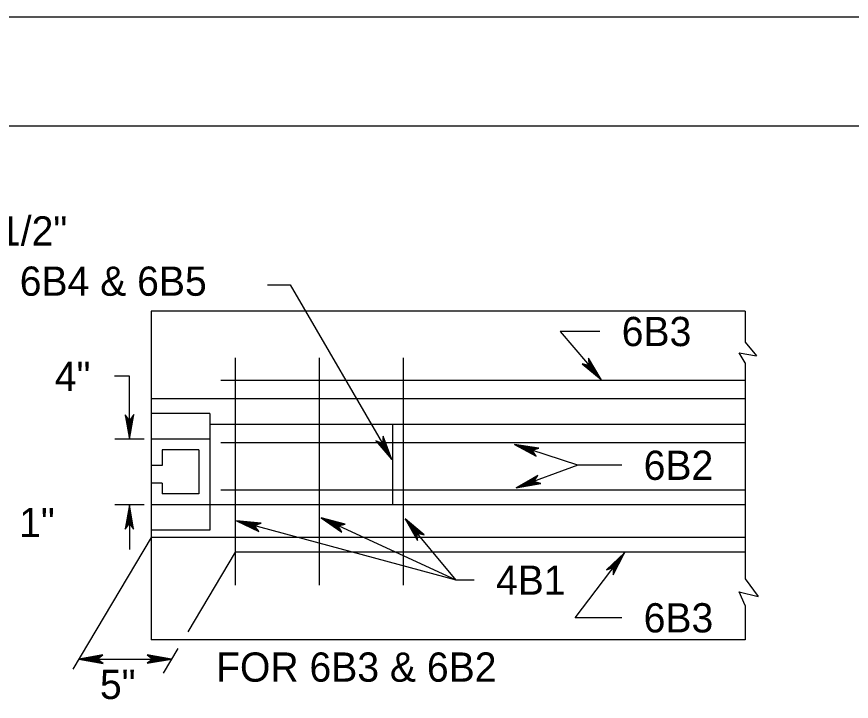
# Model space of a CAD drawing. Extents: x 499866 to 500993, y 499985 to 500645.
# Drawn here: x 500124.8 to 500238.9, y 500551.3 to 500645 of the extents above; entities that cross this region are included whole.
import ezdxf

# ---------------------------------------------------------------- set-up
doc = ezdxf.new("R2010")
doc.units = 0
for name, color, linetype in [('1', 7, 'Continuous'), ('24', 7, 'Continuous'), ('41', 7, 'Continuous'), ('5', 7, 'Continuous')]:
    doc.layers.add(name, color=color, linetype=linetype)

msp = doc.modelspace()

# ---------------------------------------------------------------- linework, layer by layer
at = {"layer": '1'}
for p, q in [((499944.83, 500645), (500993, 500645)), ((500990, 500630), (500000, 500630))]:
    msp.add_line(p, q, dxfattribs=at)
at = {"layer": '24'}
for points in [[(500204.7, 500595.36), (500202.97, 500598.29), (500203.04, 500597.3), (500202.09, 500597.52), (500204.7, 500595.36), (500204.55, 500595.53), (500203, 500598.19), (500203.08, 500597.25), (500202.21, 500597.44), (500204.46, 500595.61), (500204.4, 500595.71), (500203.07, 500597.98), (500203.09, 500597.23), (500202.35, 500597.4), (500204.37, 500595.75), (500204.28, 500595.82), (500203.12, 500597.81), (500203.11, 500597.22), (500202.5, 500597.3), (500204.07, 500596.06), (500203.95, 500596.21), (500203.17, 500597.63), (500203.14, 500597.2), (500202.67, 500597.24), (500203.94, 500596.25), (500203.83, 500596.39), (500203.21, 500597.43), (500203.19, 500597.1), (500202.85, 500597.15), (500203.72, 500596.51), (500203.62, 500596.65), (500203.26, 500597.28), (500203.21, 500597.09), (500202.95, 500597.12), (500203.55, 500596.7), (500203.33, 500597.13), (500203.28, 500597), (500203.05, 500597.07), (500203.46, 500596.78), (500203.32, 500597.06), (500203.33, 500596.9), (500203.19, 500596.97), (500203.35, 500596.92), (500203.32, 500596.99)], [(500140.18, 500587.22), (500140.78, 500590.57), (500140.18, 500589.77), (500139.6, 500590.55), (500140.18, 500587.22), (500140.18, 500587.44), (500140.73, 500590.47), (500140.18, 500589.7), (500139.65, 500590.41), (500140.17, 500587.56), (500140.18, 500587.67), (500140.65, 500590.27), (500140.18, 500589.69), (500139.72, 500590.29), (500140.18, 500587.72), (500140.17, 500587.83), (500140.58, 500590.11), (500140.18, 500589.66), (500139.78, 500590.11), (500140.17, 500588.16), (500140.17, 500588.35), (500140.49, 500589.94), (500140.19, 500589.63), (500139.86, 500589.96), (500140.18, 500588.38), (500140.19, 500588.56), (500140.4, 500589.75), (500140.17, 500589.52), (500139.94, 500589.77), (500140.18, 500588.72), (500140.2, 500588.89), (500140.34, 500589.61), (500140.18, 500589.49), (500140, 500589.69), (500140.18, 500588.98), (500140.3, 500589.45), (500140.17, 500589.38), (500140.04, 500589.59), (500140.17, 500589.1), (500140.24, 500589.4), (500140.14, 500589.28), (500140.08, 500589.42), (500140.18, 500589.28), (500140.19, 500589.35)], [(500176.06, 500584.4), (500174.89, 500587.6), (500174.78, 500586.61), (500173.88, 500586.99), (500176.06, 500584.4), (500175.94, 500584.59), (500174.9, 500587.49), (500174.8, 500586.55), (500173.99, 500586.9), (500175.87, 500584.69), (500175.83, 500584.8), (500174.93, 500587.28), (500174.81, 500586.54), (500174.12, 500586.83), (500175.81, 500584.84), (500175.73, 500584.93), (500174.95, 500587.1), (500174.83, 500586.52), (500174.25, 500586.7), (500175.57, 500585.21), (500175.48, 500585.37), (500174.96, 500586.91), (500174.86, 500586.49), (500174.4, 500586.61), (500175.47, 500585.41), (500175.39, 500585.57), (500174.97, 500586.71), (500174.89, 500586.39), (500174.56, 500586.49), (500175.3, 500585.71), (500175.23, 500585.86), (500174.99, 500586.55), (500174.91, 500586.37), (500174.66, 500586.45), (500175.17, 500585.93), (500175.04, 500586.39), (500174.96, 500586.27), (500174.74, 500586.38), (500175.1, 500586.02), (500175.01, 500586.33), (500174.99, 500586.16), (500174.86, 500586.26), (500175.02, 500586.18), (500174.99, 500586.26)], [(500192.84, 500586.47), (500195.84, 500584.87), (500195.27, 500585.68), (500196.19, 500585.99), (500192.84, 500586.47), (500193.05, 500586.41), (500195.77, 500584.94), (500195.21, 500585.7), (500196.05, 500585.99), (500193.17, 500586.38), (500193.27, 500586.33), (500195.6, 500585.08), (500195.19, 500585.71), (500195.9, 500585.96), (500193.32, 500586.31), (500193.43, 500586.29), (500195.46, 500585.2), (500195.17, 500585.71), (500195.72, 500585.96), (500193.74, 500586.19), (500193.92, 500586.13), (500195.33, 500585.33), (500195.13, 500585.71), (500195.55, 500585.93), (500193.95, 500586.11), (500194.11, 500586.04), (500195.19, 500585.48), (500195.04, 500585.77), (500195.35, 500585.91), (500194.27, 500586), (500194.43, 500585.93), (500195.07, 500585.58), (500195.01, 500585.77), (500195.25, 500585.88), (500194.52, 500585.92), (500194.93, 500585.67), (500194.9, 500585.81), (500195.14, 500585.87), (500194.63, 500585.9), (500194.9, 500585.73), (500194.81, 500585.87), (500194.97, 500585.88), (500194.8, 500585.84), (500194.87, 500585.8)], [(500193.1, 500580.54), (500196.45, 500581.14), (500195.49, 500581.42), (500196.03, 500582.24), (500193.1, 500580.54), (500193.31, 500580.62), (500196.34, 500581.15), (500195.43, 500581.4), (500195.92, 500582.15), (500193.41, 500580.67), (500193.52, 500580.7), (500196.12, 500581.16), (500195.42, 500581.4), (500195.82, 500582.03), (500193.57, 500580.71), (500193.67, 500580.77), (500195.95, 500581.17), (500195.4, 500581.38), (500195.68, 500581.92), (500193.98, 500580.88), (500194.15, 500580.94), (500195.76, 500581.19), (500195.36, 500581.36), (500195.56, 500581.79), (500194.19, 500580.94), (500194.36, 500580.99), (500195.55, 500581.21), (500195.26, 500581.35), (500195.41, 500581.65), (500194.51, 500581.06), (500194.68, 500581.1), (500195.4, 500581.22), (500195.23, 500581.33), (500195.35, 500581.57), (500194.75, 500581.15), (500195.23, 500581.2), (500195.12, 500581.3), (500195.27, 500581.49), (500194.86, 500581.2), (500195.17, 500581.24), (500195.02, 500581.29), (500195.14, 500581.4), (500195.03, 500581.26), (500195.11, 500581.27)], [(500140.18, 500578.22), (500139.59, 500574.87), (500140.18, 500575.67), (500140.77, 500574.89), (500140.18, 500578.22), (500140.19, 500578), (500139.64, 500574.97), (500140.19, 500575.74), (500140.72, 500575.03), (500140.2, 500577.88), (500140.18, 500577.77), (500139.72, 500575.17), (500140.19, 500575.75), (500140.65, 500575.15), (500140.18, 500577.72), (500140.2, 500577.61), (500139.79, 500575.34), (500140.18, 500575.78), (500140.59, 500575.33), (500140.2, 500577.28), (500140.2, 500577.09), (500139.87, 500575.5), (500140.17, 500575.81), (500140.51, 500575.48), (500140.18, 500577.06), (500140.17, 500576.88), (500139.97, 500575.69), (500140.2, 500575.92), (500140.43, 500575.67), (500140.18, 500576.72), (500140.17, 500576.55), (500140.03, 500575.83), (500140.19, 500575.95), (500140.37, 500575.75), (500140.18, 500576.46), (500140.07, 500575.99), (500140.2, 500576.06), (500140.33, 500575.86), (500140.2, 500576.34), (500140.12, 500576.04), (500140.22, 500576.17), (500140.29, 500576.02), (500140.19, 500576.16), (500140.17, 500576.09)], [(500166.42, 500576.42), (500169.22, 500574.48), (500168.74, 500575.35), (500169.69, 500575.55), (500166.42, 500576.42), (500166.63, 500576.33), (500169.15, 500574.56), (500168.69, 500575.38), (500169.55, 500575.57), (500166.74, 500576.29), (500166.84, 500576.23), (500169, 500574.72), (500168.67, 500575.39), (500169.4, 500575.55), (500166.88, 500576.21), (500166.99, 500576.17), (500168.88, 500574.85), (500168.64, 500575.39), (500169.23, 500575.58), (500167.28, 500576.04), (500167.46, 500575.96), (500168.76, 500575), (500168.61, 500575.4), (500169.05, 500575.56), (500167.48, 500575.93), (500167.64, 500575.85), (500168.64, 500575.16), (500168.53, 500575.47), (500168.85, 500575.57), (500167.79, 500575.79), (500167.94, 500575.7), (500168.53, 500575.28), (500168.49, 500575.47), (500168.74, 500575.55), (500168.02, 500575.68), (500168.4, 500575.38), (500168.39, 500575.53), (500168.63, 500575.56), (500168.14, 500575.65), (500168.38, 500575.45), (500168.31, 500575.59), (500168.47, 500575.59), (500168.3, 500575.56), (500168.36, 500575.51)], [(500154.83, 500576.03), (500157.91, 500574.59), (500157.29, 500575.37), (500158.19, 500575.72), (500154.83, 500576.03), (500155.04, 500575.98), (500157.83, 500574.65), (500157.23, 500575.39), (500158.05, 500575.72), (500155.16, 500575.96), (500155.26, 500575.91), (500157.65, 500574.79), (500157.21, 500575.39), (500157.91, 500575.68), (500155.31, 500575.9), (500155.42, 500575.89), (500157.51, 500574.9), (500157.19, 500575.39), (500157.73, 500575.67), (500155.74, 500575.8), (500155.92, 500575.75), (500157.37, 500575.02), (500157.15, 500575.39), (500157.56, 500575.63), (500155.95, 500575.73), (500156.12, 500575.67), (500157.22, 500575.16), (500157.06, 500575.45), (500157.36, 500575.6), (500156.28, 500575.64), (500156.44, 500575.58), (500157.1, 500575.26), (500157.02, 500575.44), (500157.26, 500575.57), (500156.53, 500575.57), (500156.95, 500575.34), (500156.92, 500575.48), (500157.15, 500575.55), (500156.64, 500575.56), (500156.92, 500575.4), (500156.82, 500575.53), (500156.98, 500575.55), (500156.82, 500575.5), (500156.89, 500575.46)], [(500177.89, 500576.29), (500179.58, 500573.34), (500179.53, 500574.33), (500180.48, 500574.1), (500177.89, 500576.29), (500178.04, 500576.12), (500179.56, 500573.44), (500179.49, 500574.38), (500180.35, 500574.18), (500178.12, 500576.04), (500178.18, 500575.94), (500179.49, 500573.65), (500179.48, 500574.4), (500180.21, 500574.23), (500178.22, 500575.9), (500178.3, 500575.83), (500179.44, 500573.82), (500179.46, 500574.41), (500180.06, 500574.33), (500178.51, 500575.58), (500178.63, 500575.43), (500179.4, 500574), (500179.43, 500574.43), (500179.9, 500574.39), (500178.64, 500575.4), (500178.74, 500575.25), (500179.35, 500574.2), (500179.38, 500574.53), (500179.72, 500574.48), (500178.86, 500575.13), (500178.95, 500574.99), (500179.31, 500574.35), (500179.35, 500574.55), (500179.62, 500574.51), (500179.02, 500574.94), (500179.24, 500574.5), (500179.29, 500574.64), (500179.52, 500574.56), (500179.11, 500574.86), (500179.25, 500574.57), (500179.24, 500574.73), (500179.38, 500574.66), (500179.22, 500574.71), (500179.25, 500574.64)], [(500207.92, 500571.65), (500205.42, 500569.34), (500206.37, 500569.62), (500206.36, 500568.64), (500207.92, 500571.65), (500207.79, 500571.47), (500205.51, 500569.39), (500206.42, 500569.67), (500206.41, 500568.78), (500207.72, 500571.37), (500207.64, 500571.29), (500205.7, 500569.5), (500206.43, 500569.68), (500206.43, 500568.93), (500207.61, 500571.25), (500207.56, 500571.15), (500205.86, 500569.59), (500206.44, 500569.7), (500206.49, 500569.1), (500207.36, 500570.89), (500207.25, 500570.74), (500206.02, 500569.67), (500206.45, 500569.74), (500206.51, 500569.27), (500207.21, 500570.72), (500207.1, 500570.59), (500206.21, 500569.76), (500206.53, 500569.8), (500206.56, 500569.47), (500207.01, 500570.45), (500206.89, 500570.33), (500206.35, 500569.84), (500206.55, 500569.84), (500206.57, 500569.57), (500206.85, 500570.25), (500206.48, 500569.94), (500206.62, 500569.92), (500206.6, 500569.68), (500206.79, 500570.14), (500206.55, 500569.95), (500206.7, 500569.99), (500206.66, 500569.83), (500206.68, 500570.01), (500206.62, 500569.96)], [(500133.25, 500557.11), (500136.58, 500556.53), (500135.78, 500557.11), (500136.56, 500557.69), (500133.25, 500557.11), (500133.47, 500557.12), (500136.48, 500556.57), (500135.72, 500557.12), (500136.43, 500557.65), (500133.59, 500557.13), (500133.7, 500557.11), (500136.28, 500556.66), (500135.7, 500557.12), (500136.3, 500557.57), (500133.75, 500557.11), (500133.87, 500557.13), (500136.12, 500556.72), (500135.68, 500557.11), (500136.13, 500557.52), (500134.19, 500557.13), (500134.37, 500557.13), (500135.95, 500556.81), (500135.65, 500557.1), (500135.98, 500557.43), (500134.41, 500557.11), (500134.58, 500557.1), (500135.77, 500556.9), (500135.54, 500557.13), (500135.79, 500557.36), (500134.75, 500557.11), (500134.92, 500557.1), (500135.63, 500556.96), (500135.51, 500557.12), (500135.7, 500557.3), (500135, 500557.11), (500135.47, 500557), (500135.4, 500557.13), (500135.6, 500557.26), (500135.12, 500557.13), (500135.42, 500557.05), (500135.3, 500557.15), (500135.44, 500557.21), (500135.3, 500557.12), (500135.37, 500557.1)], [(500145.94, 500557.11), (500142.62, 500557.7), (500143.41, 500557.11), (500142.63, 500556.54), (500145.94, 500557.11), (500145.72, 500557.11), (500142.71, 500557.66), (500143.47, 500557.11), (500142.77, 500556.58), (500145.6, 500557.1), (500145.49, 500557.11), (500142.91, 500557.57), (500143.49, 500557.11), (500142.89, 500556.66), (500145.44, 500557.11), (500145.33, 500557.1), (500143.07, 500557.5), (500143.51, 500557.11), (500143.06, 500556.71), (500145.01, 500557.1), (500144.82, 500557.1), (500143.24, 500557.42), (500143.55, 500557.12), (500143.22, 500556.79), (500144.79, 500557.11), (500144.61, 500557.12), (500143.42, 500557.33), (500143.65, 500557.1), (500143.4, 500556.87), (500144.44, 500557.11), (500144.28, 500557.13), (500143.56, 500557.27), (500143.68, 500557.11), (500143.49, 500556.93), (500144.19, 500557.11), (500143.73, 500557.22), (500143.79, 500557.1), (500143.59, 500556.97), (500144.07, 500557.1), (500143.77, 500557.17), (500143.9, 500557.07), (500143.75, 500557.01), (500143.9, 500557.11), (500143.82, 500557.12)]]:
    msp.add_lwpolyline(points, dxfattribs=at)
at = {"layer": '41'}
msp.add_lwpolyline([(499944.83, 500645), (500993, 500645), (500993, 499985), (499944.83, 499985)], close=True, dxfattribs=at)
at = {"layer": '5'}
for p, q in [((500224.4, 500604.7), (500143.18, 500604.7)), ((500143.18, 500604.7), (500143.18, 500559.74)), ((500224.4, 500604.7), (500224.4, 500600.47)), ((500224.4, 500600.47), (500225.96, 500598.62)), ((500154.67, 500598.31), (500154.67, 500567.22)), ((500166.16, 500598.31), (500166.16, 500567.22)), ((500177.65, 500598.31), (500177.65, 500567.22)), ((500224.4, 500597.65), (500223.59, 500599.02)), ((500223.59, 500599.02), (500225.96, 500598.62)), ((500224.4, 500597.65), (500224.4, 500568.09)), ((500224.4, 500595.21), (500152.71, 500595.21)), ((500224.4, 500592.71), (500143.18, 500592.71)), ((500151.18, 500590.71), (500143.18, 500590.71)), ((500151.18, 500590.71), (500151.18, 500578.22)), ((500224.4, 500589.22), (500151.18, 500589.22)), ((500176.16, 500589.22), (500176.16, 500578.22)), ((500142.2, 500587.22), (500138.19, 500587.22)), ((500151.18, 500587.22), (500143.18, 500587.22)), ((500224.4, 500586.72), (500152.71, 500586.72)), ((500149.68, 500585.72), (500144.68, 500585.72)), ((500144.68, 500585.72), (500144.68, 500583.58)), ((500149.68, 500585.72), (500149.68, 500579.72)), ((500201.53, 500583.63), (500192.84, 500586.47)), ((500144.68, 500583.58), (500143.18, 500583.58)), ((500201.53, 500583.63), (500193.1, 500580.54)), ((500207.52, 500583.63), (500201.53, 500583.63)), ((500144.68, 500581.18), (500143.18, 500581.18)), ((500144.68, 500581.18), (500144.68, 500579.72)), ((500149.68, 500579.72), (500144.68, 500579.72)), ((500224.4, 500580.22), (500152.71, 500580.22)), ((500142.2, 500578.22), (500138.19, 500578.22)), ((500140.18, 500578.22), (500140.18, 500572.09)), ((500151.18, 500578.22), (500143.18, 500578.22)), ((500224.4, 500578.22), (500151.18, 500578.22)), ((500151.18, 500578.22), (500151.18, 500574.73)), ((500184.88, 500567.91), (500154.83, 500576.03)), ((500184.88, 500567.91), (500177.89, 500576.29)), ((500151.18, 500574.73), (500143.18, 500574.73)), ((500143.18, 500573.73), (500132.43, 500555.73)), ((500224.4, 500573.73), (500143.18, 500573.73)), ((500154.67, 500571.73), (500148.17, 500560.86)), ((500224.4, 500571.73), (500154.67, 500571.73)), ((500224.4, 500568.09), (500226.2, 500565.67)), ((500224.4, 500564.43), (500223.59, 500566.31)), ((500223.59, 500566.31), (500226.2, 500565.67)), ((500224.4, 500564.43), (500224.4, 500559.74)), ((500224.4, 500559.74), (500143.18, 500559.74)), ((500146.81, 500558.57), (500144.79, 500555.19)), ((500133.25, 500557.11), (500145.94, 500557.11))]:
    msp.add_line(p, q, dxfattribs=at)
for points in [[(500159.06, 500608.32), (500162.18, 500608.32), (500176.06, 500584.4)], [(500204.52, 500601.93), (500199.09, 500601.93), (500204.7, 500595.36)], [(500140.18, 500587.22), (500140.18, 500595.8), (500138.13, 500595.8)], [(500187.32, 500567.91), (500184.88, 500567.91), (500166.42, 500576.42)], [(500207.52, 500562.76), (500201.15, 500562.76), (500207.92, 500571.65)]]:
    msp.add_lwpolyline(points, dxfattribs=at)

# ---------------------------------------------------------------- texts
for s, p in [('5 1/2"', (500117.89, 500613.69)), ('6B4 & 6B5', (500125.19, 500606.82)), ('6B3', (500207.52, 500599.93)), ('4"', (500129.99, 500593.8)), ('6B2', (500210.52, 500581.63)), ('1"', (500125.11, 500573.8)), ('4B1', (500190.32, 500565.91)), ('6B3', (500210.52, 500560.76)), ('FOR 6B3 & 6B2 ', (500152.04, 500554.02)), ('5"', (500136.16, 500551.65))]:
    msp.add_text(s, height=4, dxfattribs=at).set_placement(p)

doc.saveas('drawing.dxf')
